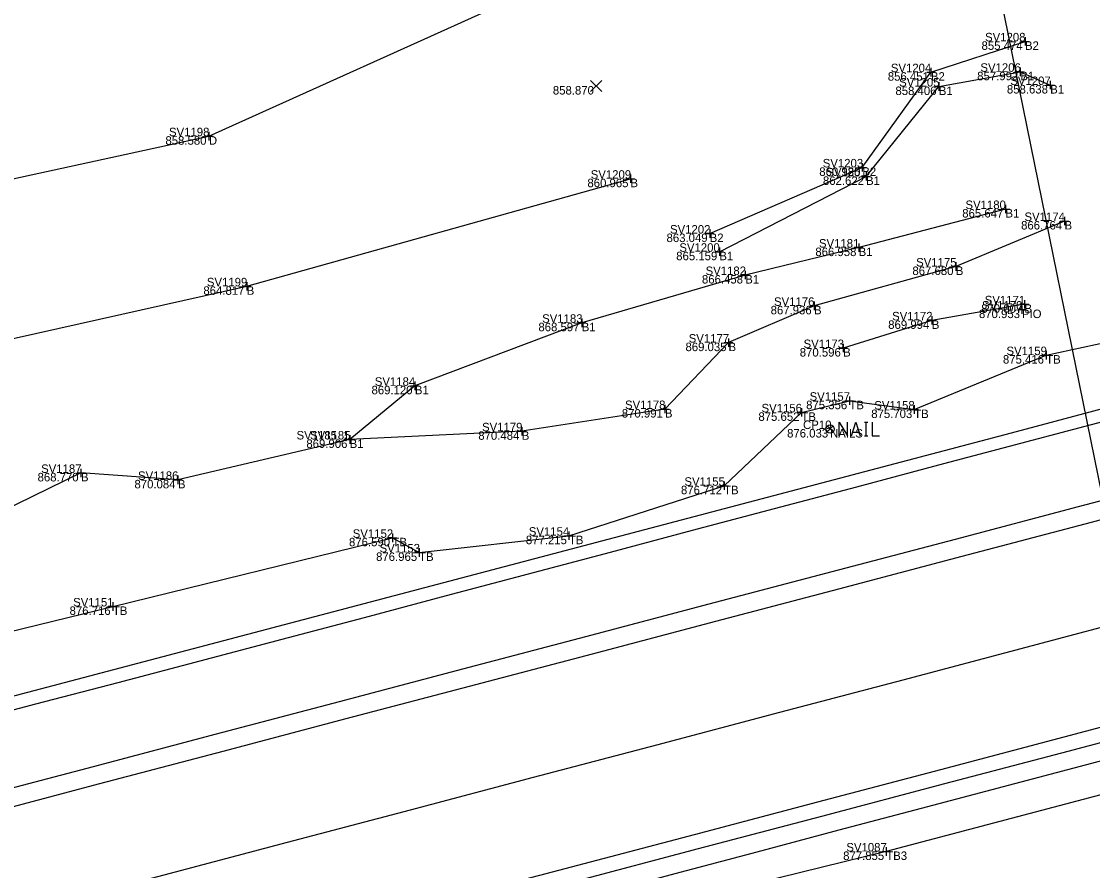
# Model space of a CAD drawing. Extents: x 2125299 to 2129212, y 713100 to 714300.
# Drawn here: x 2128168.4 to 2128294.5, y 714046 to 714146 of the extents above; entities that cross this region are included whole.
import ezdxf

# ---------------------------------------------------------------- set-up
doc = ezdxf.new("R2010")
doc.units = 0
for name, color, linetype in [('_CIVIL_CONSTRUCTION', 7, 'Continuous'), ('DR_X_Ditch', 7, 'Continuous'), ('DR_X_Storm_Sewer', 7, 'Continuous'), ('PV_X_EOP', 7, 'Continuous'), ('PV_X_Shoulder_Rumble_Strip', 7, 'Continuous'), ('RW_P_Esmt_TMP', 7, 'Continuous'), ('RW_X_CL_100_Cardinal_Points', 7, 'Continuous'), ('RW_X_Esmt_CH', 7, 'Continuous'), ('RW_X_Fee_WL', 7, 'Continuous'), ('SC_Scratch1', 7, 'Continuous'), ('SC_Scratch2', 7, 'Continuous'), ('SV_X_Break_Lines', 7, 'Continuous'), ('SV_X_Mon_Cells_Found', 7, 'Continuous'), ('SV_X_Text_Elevation', 7, 'Continuous'), ('SV_X_Text_Name', 7, 'Continuous'), ('SV_X_Top_of_Bank', 7, 'Continuous')]:
    doc.layers.add(name, color=color, linetype=linetype)

msp = doc.modelspace()

# ---------------------------------------------------------------- linework, layer by layer
at = {"layer": '_CIVIL_CONSTRUCTION'}
msp.add_lwpolyline([(2128156.2, 714037.91), (2128170.7, 714041.73), (2128185.21, 714045.56), (2128199.71, 714049.38), (2128214.22, 714053.21), (2128228.72, 714057.03), (2128243.22, 714060.86), (2128257.73, 714064.68), (2128272.23, 714068.51), (2128286.73, 714072.34), (2128301.23, 714076.18), (2128315.73, 714080.03), (2128330.23, 714083.87), (2128344.73, 714087.71), (2128359.23, 714091.55), (2128373.73, 714095.39), (2128388.23, 714099.23), (2128402.73, 714103.07), (2128417.23, 714106.91)], dxfattribs=at)
at = {"layer": 'DR_X_Ditch'}
msp.add_lwpolyline([(2128126.02, 714119.43), (2128165.52, 714127.08), (2128190.47, 714132.5), (2128226.54, 714148.8), (2128253.76, 714161.24), (2128264.19, 714163.45), (2128277.88, 714165.58), (2128280.71, 714165.85)], dxfattribs=at)
at = {"layer": 'DR_X_Storm_Sewer'}
msp.add_line((2128282.88, 714152.99), (2128337.68, 713883.12), dxfattribs=at)
at = {"layer": 'PV_X_EOP'}
for points in [[(2128160.43, 714063.11), (2128170.1, 714065.66), (2128179.77, 714068.2), (2128189.44, 714070.75), (2128199.11, 714073.29), (2128208.78, 714075.85), (2128218.44, 714078.41), (2128228.11, 714080.98), (2128237.77, 714083.54), (2128247.44, 714086.11), (2128257.1, 714088.67), (2128266.77, 714091.24), (2128276.43, 714093.81), (2128286.1, 714096.37), (2128295.77, 714098.93)], [(2128168.1, 714025.06), (2128177.78, 714027.55), (2128187.45, 714030.11), (2128197.11, 714032.71), (2128206.76, 714035.31), (2128216.42, 714037.91), (2128226.07, 714040.51), (2128235.73, 714043.11), (2128245.39, 714045.7), (2128255.06, 714048.26), (2128264.72, 714050.82), (2128274.39, 714053.38), (2128284.06, 714055.94), (2128293.72, 714058.5), (2128303.39, 714061.06)]]:
    msp.add_lwpolyline(points, dxfattribs=at)
at = {"layer": 'PV_X_Shoulder_Rumble_Strip'}
for points in [[(2128099.62, 714037.93), (2128104.35, 714039.18), (2128118.85, 714043), (2128133.35, 714046.83), (2128147.86, 714050.65), (2128162.36, 714054.48), (2128176.86, 714058.3), (2128191.37, 714062.13), (2128205.87, 714065.95), (2128220.37, 714069.78), (2128234.88, 714073.6), (2128249.38, 714077.43), (2128263.89, 714081.25), (2128278.39, 714085.07), (2128292.89, 714088.9), (2128307.4, 714092.72), (2128321.9, 714096.55), (2128336.4, 714100.37), (2128350.91, 714104.2), (2128365.41, 714108.02), (2128379.92, 714111.85), (2128394.42, 714115.67), (2128408.92, 714119.5), (2128423.43, 714123.32)], [(2128092.76, 714007.7), (2128103.1, 714010.43), (2128117.61, 714014.25), (2128132.11, 714018.07), (2128146.62, 714021.89), (2128161.12, 714025.71), (2128175.62, 714029.53), (2128190.13, 714033.35), (2128204.63, 714037.17), (2128219.14, 714040.99), (2128233.64, 714044.81), (2128248.15, 714048.63), (2128262.65, 714052.45), (2128277.16, 714056.28), (2128291.66, 714060.12), (2128306.16, 714063.95), (2128320.66, 714067.79), (2128335.16, 714071.62), (2128349.66, 714075.46), (2128364.16, 714079.29), (2128378.66, 714083.13), (2128393.16, 714086.96), (2128407.66, 714090.8), (2128422.17, 714094.63)]]:
    msp.add_lwpolyline(points, dxfattribs=at)
at = {"layer": 'RW_X_CL_100_Cardinal_Points'}
for p, q in [((2128285.73, 714112.09), (2128286.73, 714112.09)), ((2128286.23, 714112.59), (2128286.23, 714111.59)), ((2128286.23, 714112.09), (2128286.23, 714112.09))]:
    msp.add_line(p, q, dxfattribs=at)
at = {"layer": 'SC_Scratch1'}
msp.add_lwpolyline([(2128628.95, 714194.22), (2128585.4, 714182.79), (2128564.12, 714177.04), (2128556.66, 714174.91), (2128549.07, 714172.15), (2128542.5, 714169.81), (2128530.23, 714165.43), (2128519.08, 714161.63), (2128507.97, 714157.87), (2128491.85, 714153.02), (2128450.41, 714141.74), (2128284.96, 714097.53), (2128098.63, 714048.44)], dxfattribs=at)
at = {"layer": 'SC_Scratch2'}
for points in [[(2128163.14, 714052.45), (2128177.64, 714056.28), (2128192.15, 714060.1), (2128206.65, 714063.93), (2128221.16, 714067.75), (2128235.66, 714071.58), (2128250.17, 714075.4), (2128264.67, 714079.23), (2128279.17, 714083.05), (2128293.68, 714086.88), (2128308.18, 714090.7), (2128322.69, 714094.53), (2128337.19, 714098.35), (2128351.69, 714102.18), (2128366.2, 714106), (2128380.7, 714109.83), (2128395.21, 714113.65), (2128409.71, 714117.48), (2128424.21, 714121.3)], [(2128160.65, 714027.38), (2128175.15, 714031.2), (2128189.66, 714035.02), (2128204.16, 714038.84), (2128218.67, 714042.66), (2128233.17, 714046.48), (2128247.68, 714050.3), (2128262.18, 714054.12), (2128276.69, 714057.95), (2128291.19, 714061.78), (2128305.69, 714065.62), (2128320.19, 714069.46), (2128334.69, 714073.29), (2128349.19, 714077.13), (2128363.69, 714080.96), (2128378.2, 714084.8), (2128392.7, 714088.63), (2128407.2, 714092.47), (2128421.7, 714096.3)]]:
    msp.add_lwpolyline(points, dxfattribs=at)
at = {"layer": 'SV_X_Break_Lines'}
for p, q in [((2128289.56, 714138.53), (2128289.56, 714138.53)), ((2128291.25, 714122.52), (2128291.25, 714122.52)), ((2128250.59, 714118.9), (2128250.59, 714118.9)), ((2128278.44, 714117.16), (2128278.44, 714117.16)), ((2128261.74, 714112.53), (2128261.74, 714112.53)), ((2128251.67, 714108.2), (2128251.67, 714108.2)), ((2128244.18, 714100.38), (2128244.18, 714100.38))]:
    msp.add_line(p, q, dxfattribs=at)
for points in [[(2128249.45, 714121.04), (2128267.43, 714128.83), (2128275.51, 714140.04), (2128286.59, 714143.67)], [(2128250.59, 714118.9), (2128267.87, 714127.77), (2128276.44, 714138.35), (2128286.04, 714140.09), (2128289.56, 714138.53)], [(2128120.14, 714107.52), (2128150.37, 714104.88), (2128194.92, 714114.83), (2128240.12, 714127.5)], [(2128284.29, 714123.93), (2128267, 714119.39), (2128253.64, 714116.16), (2128234.38, 714110.54), (2128214.73, 714103.12), (2128207.05, 714096.8)], [(2128291.25, 714122.52), (2128278.44, 714117.16), (2128261.74, 714112.53), (2128251.67, 714108.2), (2128244.18, 714100.38), (2128227.32, 714097.76), (2128207.05, 714096.8), (2128186.82, 714092.04), (2128175.4, 714092.86), (2128158.35, 714084.54), (2128142.67, 714079.79), (2128121.38, 714073.43), (2128106.87, 714068.79)], [(2128286.53, 714112.71), (2128275.61, 714110.82), (2128265.17, 714107.56)]]:
    msp.add_lwpolyline(points, dxfattribs=at)
at = {"layer": 'SV_X_Mon_Cells_Found'}
for p, q in [((2128286.09, 714143.67), (2128287.09, 714143.67)), ((2128286.59, 714144.17), (2128286.59, 714143.17)), ((2128286.59, 714143.67), (2128286.59, 714143.67)), ((2128275.51, 714140.54), (2128275.51, 714139.54)), ((2128286.04, 714140.59), (2128286.04, 714139.59)), ((2128275.01, 714140.04), (2128276.01, 714140.04)), ((2128275.51, 714140.04), (2128275.51, 714140.04)), ((2128285.54, 714140.09), (2128286.54, 714140.09)), ((2128286.04, 714140.09), (2128286.04, 714140.09)), ((2128275.94, 714138.35), (2128276.94, 714138.35)), ((2128276.44, 714138.85), (2128276.44, 714137.85)), ((2128276.44, 714138.35), (2128276.44, 714138.35)), ((2128289.06, 714138.53), (2128290.06, 714138.53)), ((2128289.56, 714139.03), (2128289.56, 714138.03)), ((2128289.56, 714138.53), (2128289.56, 714138.53)), ((2128190.47, 714133), (2128190.47, 714132)), ((2128189.97, 714132.5), (2128190.97, 714132.5)), ((2128190.47, 714132.5), (2128190.47, 714132.5)), ((2128267.43, 714129.33), (2128267.43, 714128.33)), ((2128240.12, 714128), (2128240.12, 714127)), ((2128266.93, 714128.83), (2128267.93, 714128.83)), ((2128267.43, 714128.83), (2128267.43, 714128.83)), ((2128267.87, 714128.27), (2128267.87, 714127.27)), ((2128239.62, 714127.5), (2128240.62, 714127.5)), ((2128240.12, 714127.5), (2128240.12, 714127.5)), ((2128267.37, 714127.77), (2128268.37, 714127.77)), ((2128267.87, 714127.77), (2128267.87, 714127.77)), ((2128284.29, 714124.43), (2128284.29, 714123.43)), ((2128283.79, 714123.93), (2128284.79, 714123.93)), ((2128284.29, 714123.93), (2128284.29, 714123.93)), ((2128291.25, 714123.02), (2128291.25, 714122.02)), ((2128249.45, 714121.54), (2128249.45, 714120.54)), ((2128290.75, 714122.52), (2128291.75, 714122.52)), ((2128291.25, 714122.52), (2128291.25, 714122.52)), ((2128248.95, 714121.04), (2128249.95, 714121.04)), ((2128249.45, 714121.04), (2128249.45, 714121.04)), ((2128250.59, 714119.4), (2128250.59, 714118.4)), ((2128266.5, 714119.39), (2128267.5, 714119.39)), ((2128267, 714119.89), (2128267, 714118.89)), ((2128267, 714119.39), (2128267, 714119.39)), ((2128250.09, 714118.9), (2128251.09, 714118.9)), ((2128250.59, 714118.9), (2128250.59, 714118.9)), ((2128253.64, 714116.66), (2128253.64, 714115.66)), ((2128277.94, 714117.16), (2128278.94, 714117.16)), ((2128278.44, 714117.66), (2128278.44, 714116.66)), ((2128278.44, 714117.16), (2128278.44, 714117.16)), ((2128194.92, 714115.33), (2128194.92, 714114.33)), ((2128253.14, 714116.16), (2128254.14, 714116.16)), ((2128253.64, 714116.16), (2128253.64, 714116.16)), ((2128194.42, 714114.83), (2128195.42, 714114.83)), ((2128194.92, 714114.83), (2128194.92, 714114.83)), ((2128261.74, 714113.03), (2128261.74, 714112.03)), ((2128286.03, 714112.71), (2128287.03, 714112.71)), ((2128286.53, 714113.21), (2128286.53, 714112.21)), ((2128286.53, 714112.71), (2128286.53, 714112.71)), ((2128261.24, 714112.53), (2128262.24, 714112.53)), ((2128261.74, 714112.53), (2128261.74, 714112.53)), ((2128233.88, 714110.54), (2128234.88, 714110.54)), ((2128234.38, 714111.04), (2128234.38, 714110.04)), ((2128234.38, 714110.54), (2128234.38, 714110.54)), ((2128275.11, 714110.82), (2128276.11, 714110.82)), ((2128275.61, 714111.32), (2128275.61, 714110.32)), ((2128275.61, 714110.82), (2128275.61, 714110.82)), ((2128251.17, 714108.2), (2128252.17, 714108.2)), ((2128251.67, 714108.7), (2128251.67, 714107.7)), ((2128251.67, 714108.2), (2128251.67, 714108.2)), ((2128265.17, 714108.06), (2128265.17, 714107.06)), ((2128264.67, 714107.56), (2128265.67, 714107.56)), ((2128265.17, 714107.56), (2128265.17, 714107.56)), ((2128288.59, 714106.73), (2128289.59, 714106.73)), ((2128289.09, 714107.23), (2128289.09, 714106.23)), ((2128289.09, 714106.73), (2128289.09, 714106.73)), ((2128214.23, 714103.12), (2128215.23, 714103.12)), ((2128214.73, 714103.62), (2128214.73, 714102.62)), ((2128214.73, 714103.12), (2128214.73, 714103.12)), ((2128265.41, 714101.36), (2128266.41, 714101.36)), ((2128265.91, 714101.86), (2128265.91, 714100.86)), ((2128265.91, 714101.36), (2128265.91, 714101.36)), ((2128243.68, 714100.38), (2128244.68, 714100.38)), ((2128244.18, 714100.88), (2128244.18, 714099.88)), ((2128244.18, 714100.38), (2128244.18, 714100.38)), ((2128260.26, 714100.49), (2128260.26, 714099.49)), ((2128273.04, 714100.32), (2128274.04, 714100.32)), ((2128273.54, 714100.82), (2128273.54, 714099.82)), ((2128273.54, 714100.32), (2128273.54, 714100.32)), ((2128259.76, 714099.99), (2128260.76, 714099.99)), ((2128260.26, 714099.99), (2128260.26, 714099.99)), ((2128226.82, 714097.76), (2128227.82, 714097.76)), ((2128227.32, 714098.26), (2128227.32, 714097.26)), ((2128227.32, 714097.76), (2128227.32, 714097.76)), ((2128206.55, 714096.8), (2128207.55, 714096.8)), ((2128206.55, 714096.8), (2128207.55, 714096.8)), ((2128207.05, 714097.3), (2128207.05, 714096.3)), ((2128207.05, 714097.3), (2128207.05, 714096.3)), ((2128207.05, 714096.8), (2128207.05, 714096.8)), ((2128207.05, 714096.8), (2128207.05, 714096.8)), ((2128174.9, 714092.86), (2128175.9, 714092.86)), ((2128175.4, 714093.36), (2128175.4, 714092.36)), ((2128175.4, 714092.86), (2128175.4, 714092.86)), ((2128186.82, 714092.54), (2128186.82, 714091.54)), ((2128186.32, 714092.04), (2128187.32, 714092.04)), ((2128186.82, 714092.04), (2128186.82, 714092.04)), ((2128250.65, 714091.35), (2128251.65, 714091.35)), ((2128251.15, 714091.85), (2128251.15, 714090.85)), ((2128251.15, 714091.35), (2128251.15, 714091.35)), ((2128211.59, 714085.22), (2128212.59, 714085.22)), ((2128212.09, 714085.72), (2128212.09, 714084.72)), ((2128212.09, 714085.22), (2128212.09, 714085.22)), ((2128232.37, 714085.47), (2128233.37, 714085.47)), ((2128232.87, 714085.97), (2128232.87, 714084.97)), ((2128232.87, 714085.47), (2128232.87, 714085.47)), ((2128215.23, 714084), (2128215.23, 714083)), ((2128214.73, 714083.5), (2128215.73, 714083.5)), ((2128215.23, 714083.5), (2128215.23, 714083.5)), ((2128179.16, 714077.64), (2128179.16, 714076.64)), ((2128178.66, 714077.14), (2128179.66, 714077.14)), ((2128179.16, 714077.14), (2128179.16, 714077.14)), ((2128270.25, 714048.79), (2128270.25, 714047.79)), ((2128269.75, 714048.29), (2128270.75, 714048.29)), ((2128270.25, 714048.29), (2128270.25, 714048.29))]:
    msp.add_line(p, q, dxfattribs=at)
at = {"layer": 'SV_X_Text_Elevation'}
for p, q in [((2128235.42, 714137.75), (2128236.76, 714139.08)), ((2128235.42, 714139.08), (2128236.76, 714137.75))]:
    msp.add_line(p, q, dxfattribs=at)
at = {"layer": 'SV_X_Text_Name'}
for p, q in [((2128263.28, 714098.39), (2128263.99, 714097.68)), ((2128263.28, 714097.68), (2128263.99, 714098.39))]:
    msp.add_line(p, q, dxfattribs=at)
for points in [[(2128264.72, 714097.23), (2128264.72, 714098.83), (2128265.67, 714097.23), (2128265.67, 714098.83)], [(2128266.17, 714097.23), (2128266.67, 714098.83), (2128267.17, 714097.23)], [(2128267.67, 714098.83), (2128268.07, 714098.83)], [(2128267.87, 714097.23), (2128267.87, 714098.83)], [(2128268.58, 714098.83), (2128268.58, 714097.23), (2128269.45, 714097.23)], [(2128267.04, 714097.6), (2128266.3, 714097.6)], [(2128267.67, 714097.23), (2128268.07, 714097.23)]]:
    msp.add_lwpolyline(points, dxfattribs=at)
msp.add_circle((2128263.63, 714098.03), 0.5, dxfattribs=at)
at = {"layer": 'SV_X_Top_of_Bank'}
for points in [[(2128105.46, 714054.71), (2128114.11, 714060.74), (2128124.65, 714063.56), (2128152.61, 714070.67), (2128179.16, 714077.14), (2128212.09, 714085.22), (2128215.23, 714083.5), (2128232.87, 714085.47), (2128251.15, 714091.35), (2128260.26, 714099.99), (2128265.91, 714101.36), (2128273.54, 714100.32), (2128289.09, 714106.73), (2128315.22, 714112.36), (2128351.86, 714121.53), (2128391.6, 714133.45), (2128421.6, 714142.07), (2128443.7, 714149.09)], [(2128621.75, 714139.89), (2128575.4, 714127.43), (2128536.54, 714118.82), (2128494.56, 714106.73), (2128494.59, 714106.74), (2128431.42, 714092.25), (2128387.26, 714080.92), (2128325.7, 714062.91), (2128270.25, 714048.29), (2128232.44, 714039), (2128192.57, 714028.85), (2128120.54, 714010.42)]]:
    msp.add_lwpolyline(points, dxfattribs=at)

# ---------------------------------------------------------------- texts
at = {"layer": 'RW_P_Esmt_TMP'}
for s, p in [('B2', (2128286.59, 714142.67)), ('B2', (2128275.51, 714139.04)), ('B1', (2128286.04, 714139.09)), ('B1', (2128276.44, 714137.35)), ('B1', (2128289.56, 714137.53)), ('D', (2128190.47, 714131.5)), ('B2', (2128267.43, 714127.83)), ('B', (2128240.12, 714126.5)), ('B1', (2128267.87, 714126.77)), ('B1', (2128284.29, 714122.93)), ('B', (2128291.25, 714121.52)), ('B2', (2128249.45, 714120.04)), ('B1', (2128267, 714118.39)), ('B1', (2128250.59, 714117.9)), ('B', (2128278.44, 714116.16)), ('B1', (2128253.64, 714115.16)), ('B', (2128194.92, 714113.83)), ('B', (2128286.53, 714111.71)), ('B', (2128261.74, 714111.53)), ('PIO', (2128286.23, 714111.09)), ('B1', (2128234.38, 714109.54)), ('B', (2128275.61, 714109.82)), ('B', (2128251.67, 714107.2)), ('B', (2128265.17, 714106.56)), ('TB', (2128289.09, 714105.73)), ('B1', (2128214.73, 714102.12)), ('TB', (2128265.91, 714100.36)), ('B', (2128244.18, 714099.38)), ('TB', (2128273.54, 714099.32)), ('TB', (2128260.26, 714098.99)), ('B', (2128227.32, 714096.76)), ('NAILS', (2128263.63, 714097.03)), ('B1', (2128207.05, 714095.8)), ('B', (2128207.05, 714095.8)), ('B', (2128175.4, 714091.86)), ('B', (2128186.82, 714091.04)), ('TB', (2128251.15, 714090.35)), ('TB', (2128212.09, 714084.22)), ('TB', (2128232.87, 714084.47)), ('TB', (2128215.23, 714082.5)), ('TB', (2128179.16, 714076.14)), ('TB3', (2128270.25, 714047.29))]:
    msp.add_text(s, height=1, dxfattribs=at).set_placement(p)
at = {"layer": 'RW_X_Esmt_CH'}
for s, p in [('SV1208', (2128281.89, 714143.67)), ('SV1204', (2128270.79, 714140.04)), ('SV1206', (2128281.34, 714140.09)), ('SV1205', (2128271.77, 714138.35)), ('SV1207', (2128284.86, 714138.53)), ('SV1198', (2128185.77, 714132.5)), ('SV1203', (2128262.77, 714128.83)), ('SV1209', (2128235.44, 714127.5)), ('SV1201', (2128263.19, 714127.77)), ('SV1180', (2128279.58, 714123.93)), ('SV1174', (2128286.53, 714122.52)), ('SV1202', (2128244.78, 714121.04)), ('SV1181', (2128262.32, 714119.39)), ('SV1200', (2128245.88, 714118.9)), ('SV1175', (2128273.77, 714117.16)), ('SV1182', (2128248.97, 714116.16)), ('SV1199', (2128190.23, 714114.83)), ('SV1176', (2128257.03, 714112.53)), ('SV1170', (2128281.52, 714112.09)), ('SV1171', (2128281.85, 714112.71)), ('SV1183', (2128229.72, 714110.54)), ('SV1172', (2128270.94, 714110.82)), ('SV1177', (2128246.98, 714108.2)), ('SV1173', (2128260.51, 714107.56)), ('SV1159', (2128284.41, 714106.73)), ('SV1184', (2128210.01, 714103.12)), ('SV1178', (2128239.48, 714100.38)), ('SV1157', (2128261.22, 714101.36)), ('SV1156', (2128255.56, 714099.99)), ('SV1158', (2128268.84, 714100.32)), ('CP10', (2128260.45, 714098.03)), ('SV1185_1', (2128200.79, 714096.8)), ('SV1185', (2128202.38, 714096.8)), ('SV1179', (2128222.64, 714097.76)), ('SV1187', (2128170.71, 714092.86)), ('SV1186', (2128182.12, 714092.04)), ('SV1155', (2128246.48, 714091.35)), ('SV1152', (2128207.41, 714085.22)), ('SV1154', (2128228.15, 714085.47)), ('SV1153', (2128210.57, 714083.5)), ('SV1151', (2128174.48, 714077.14)), ('SV1087', (2128265.55, 714048.29))]:
    msp.add_text(s, height=1, dxfattribs=at).set_placement(p)
at = {"layer": 'RW_X_Fee_WL'}
for s, p in [('855.474', (2128281.47, 714142.67)), ('856.451', (2128270.43, 714139.04)), ('857.992', (2128280.96, 714139.09)), ('858.870', (2128230.98, 714137.41)), ('858.406', (2128271.33, 714137.35)), ('858.638', (2128284.46, 714137.53)), ('858.580', (2128185.35, 714131.5)), ('860.985', (2128262.36, 714127.83)), ('860.965', (2128235.05, 714126.5)), ('862.622', (2128262.79, 714126.77)), ('865.647', (2128279.2, 714122.93)), ('866.764', (2128286.13, 714121.52)), ('863.049', (2128244.37, 714120.04)), ('866.958', (2128261.9, 714118.39)), ('865.159', (2128245.51, 714117.9)), ('867.680', (2128273.33, 714116.16)), ('866.458', (2128248.54, 714115.16)), ('864.817', (2128189.82, 714113.83)), ('870.007', (2128281.43, 714111.71)), ('867.936', (2128256.63, 714111.53)), ('870.953', (2128281.17, 714111.09)), ('868.597', (2128229.28, 714109.54)), ('869.994', (2128270.48, 714109.82)), ('869.035', (2128246.6, 714107.2)), ('870.596', (2128260.06, 714106.56)), ('875.416', (2128283.99, 714105.73)), ('869.120', (2128209.62, 714102.12)), ('875.356', (2128260.81, 714100.36)), ('870.991', (2128239.1, 714099.38)), ('875.703', (2128268.48, 714099.32)), ('875.652', (2128255.19, 714098.99)), ('870.484', (2128222.2, 714096.76)), ('876.033', (2128258.57, 714097.03)), ('869.906', (2128201.95, 714095.8)), ('869.906', (2128201.95, 714095.8)), ('868.770', (2128170.29, 714091.86)), ('870.084', (2128181.7, 714091.04)), ('876.712', (2128246.07, 714090.35)), ('876.590', (2128206.97, 714084.22)), ('877.215', (2128227.8, 714084.47)), ('876.965', (2128210.16, 714082.5)), ('876.716', (2128174.06, 714076.14)), ('877.855', (2128265.17, 714047.29))]:
    msp.add_text(s, height=1, dxfattribs=at).set_placement(p)

doc.saveas('drawing.dxf')
